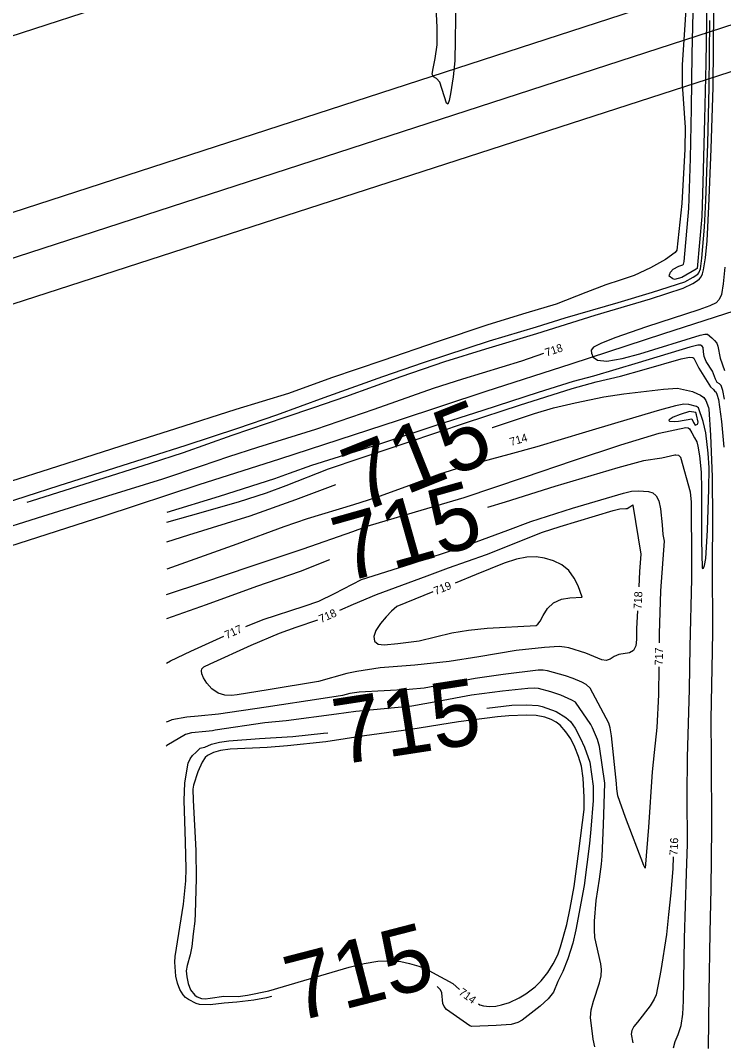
# Model space of a CAD drawing. Extents: x -468556195 to 3353078, y -306091294 to 1252632.
# Drawn here: x 1829375 to 1829727, y 533219 to 533730 of the extents above; entities that cross this region are included whole.
import ezdxf

# ---------------------------------------------------------------- set-up
doc = ezdxf.new("R2010")
doc.units = 0
for name, color, linetype in [('Default', 7, 'Continuous'), ('DT_X_Contour_Minor', 7, 'Continuous'), ('Level 14', 7, 'Continuous'), ('Level 19', 7, 'Continuous'), ('SC_Shading3', 7, 'Continuous')]:
    doc.layers.add(name, color=color, linetype=linetype)

msp = doc.modelspace()

# ---------------------------------------------------------------- linework, layer by layer
at = {"layer": 'Default'}
msp.add_lwpolyline([(1827162.83, 532893.73), (1827168.81, 532875.29), (1833162.58, 534815.33), (1833154.87, 534839.74)], close=True, dxfattribs=at)
at = {"layer": 'DT_X_Contour_Minor'}
for points in [[(1829593.13, 533741.62), (1829592.52, 533709.77), (1829591.78, 533701.79), (1829590.46, 533693.14), (1829589.79, 533689.85), (1829589.1, 533688.08), (1829588.36, 533688.52), (1829585.06, 533699.08), (1829583.38, 533700.83), (1829581.9, 533701.67), (1829581.22, 533702.98), (1829581.7, 533705.94), (1829582.79, 533710.83), (1829583.69, 533717.68), (1829583.81, 533726.32), (1829582.3, 533757.27)], [(1829378.72, 533489.09), (1829380.91, 533489.79), (1829410.96, 533499.28), (1829440.36, 533508.53), (1829456.98, 533513.89), (1829481.21, 533522.55), (1829507.71, 533531.63), (1829522.13, 533536.44), (1829538.11, 533541.92), (1829565.71, 533551.87), (1829587.59, 533559.36), (1829608.12, 533565.77), (1829633.62, 533573.4), (1829662.76, 533582.52), (1829690.41, 533590.8), (1829706.72, 533596.08), (1829711.56, 533598.35), (1829713.88, 533599.83), (1829714.84, 533600.65), (1829715.67, 533601.69), (1829716.36, 533603.18), (1829716.93, 533605.28), (1829717.83, 533611.29), (1829718.62, 533619.69), (1829719.59, 533636.83), (1829720.65, 533665.7), (1829721.64, 533696.62), (1829721.81, 533716.38), (1829722.15, 533752.87)], [(1829708.39, 533741.08), (1829707.56, 533727.79), (1829706.13, 533707.75), (1829706.23, 533697.89), (1829707.7, 533676.46), (1829707.48, 533665.58), (1829706.06, 533638.36), (1829703.51, 533615.12), (1829702.76, 533613.83), (1829697.94, 533610.42), (1829690.35, 533606.16), (1829682.12, 533602.4), (1829675.13, 533600.01), (1829668.05, 533597.7), (1829658.12, 533593.93), (1829643.22, 533588.14), (1829628.04, 533583.56), (1829609.05, 533577.7), (1829583.8, 533569.27), (1829556.59, 533559.93), (1829530.97, 533551.16), (1829509.35, 533543.36), (1829483.02, 533535.34), (1829452.87, 533525.69), (1829425.66, 533517.12), (1829393.98, 533506.94), (1829366.76, 533498.24)], [(1829718.54, 533740.23), (1829717.94, 533708.57), (1829717.39, 533680.55), (1829716.57, 533649.02), (1829715.97, 533631.83), (1829713.61, 533605.93), (1829713.16, 533605.56), (1829705.98, 533601.39), (1829702.3, 533600.4), (1829701.54, 533600.67), (1829699.68, 533602.02), (1829699.8, 533602.77), (1829700.39, 533604.08), (1829701.76, 533605.5), (1829704.56, 533607.06), (1829706.55, 533607.66), (1829706.92, 533608.07), (1829707.17, 533609.36), (1829709.53, 533635.89), (1829710.31, 533660.95), (1829710.85, 533685.8), (1829711.17, 533713.12), (1829711.9, 533741.05)], [(1829361.65, 533486.79), (1829394.74, 533497.34), (1829422.62, 533506.16), (1829458.2, 533517.49), (1829484.15, 533526.01), (1829503.57, 533532.66), (1829527.32, 533541.36), (1829556.6, 533551.94), (1829576.88, 533558.97), (1829609.82, 533569.67), (1829633.38, 533576.81), (1829647.71, 533581.21), (1829674.24, 533588.83), (1829691.31, 533593.98), (1829707.53, 533599.25), (1829711.76, 533601.6), (1829714, 533603.1), (1829714.59, 533603.75), (1829715.3, 533605.76), (1829715.96, 533610.98), (1829717.33, 533626.63), (1829718.02, 533639.88), (1829718.97, 533668.33), (1829719.64, 533696.58), (1829719.99, 533729.95)], [(1829727.57, 533606.61), (1829726.73, 533598.3), (1829725.78, 533592.93), (1829724.74, 533590.46), (1829723.19, 533588.77), (1829720.03, 533587.21), (1829714.44, 533585.16), (1829688.39, 533576.66), (1829672.61, 533571.15), (1829665.58, 533568.43), (1829661.79, 533566.51), (1829660.64, 533565.05), (1829660.9, 533563.53), (1829661.75, 533561.63), (1829663.94, 533560.02), (1829668.6, 533559.6), (1829676.27, 533560.94), (1829685.09, 533563.29), (1829715.18, 533572.57), (1829717.6, 533573.11), (1829718.88, 533573.01), (1829721.06, 533571.3), (1829722.38, 533569.96), (1829723.45, 533568.51), (1829724.01, 533567.06), (1829725.2, 533561.05), (1829727.34, 533554.88)], [(1829727.31, 533540.6), (1829726.47, 533544.97), (1829725.63, 533547.34), (1829724.82, 533548.25), (1829723.64, 533548.98), (1829722.91, 533550.53), (1829721.29, 533554.63), (1829718.24, 533559.38), (1829717.15, 533561.87), (1829716.85, 533564.24), (1829716.62, 533566.41), (1829716.17, 533567.12), (1829715.35, 533567.51), (1829714.09, 533567.54), (1829709.98, 533566.55), (1829684.2, 533558.75), (1829661.79, 533552.13), (1829651.65, 533549.46), (1829634.13, 533543.91), (1829606.5, 533534.95), (1829583.04, 533527.32), (1829554.42, 533517.96), (1829520.99, 533507.38), (1829509.71, 533503.45), (1829502.34, 533500.72), (1829474.75, 533491.94), (1829448.63, 533483.94)], [(1829340.43, 533467.61), (1829359.01, 533473.44), (1829386.56, 533482.07), (1829419.13, 533492.22), (1829446.62, 533500.73), (1829466, 533507.16), (1829479.52, 533511.96), (1829494.08, 533516.58), (1829523.05, 533525.58), (1829552.25, 533535.63), (1829581.87, 533546.04), (1829596.49, 533550.81), (1829626.01, 533559.81), (1829637.09, 533563.48)], [(1829448.61, 533479.07), (1829460.36, 533482.46), (1829484.44, 533489.21), (1829498.47, 533493.74), (1829508.3, 533497.4), (1829529.43, 533505.76), (1829545.26, 533511.12), (1829568.67, 533518.96), (1829598.46, 533528.87), (1829624.91, 533537.64), (1829651.29, 533545.97), (1829663.26, 533549.15), (1829675.43, 533552.12), (1829687.15, 533555.46), (1829705.64, 533560.81), (1829709.8, 533561.55), (1829711.53, 533561.43), (1829712.02, 533561.1), (1829712.92, 533559.45), (1829714.45, 533556.09), (1829720.35, 533546.67), (1829721.79, 533545.37), (1829722.47, 533544.48), (1829722.96, 533544.15), (1829723.59, 533543.11), (1829724.31, 533540.4), (1829725.83, 533529.44), (1829727.03, 533516.51)], [(1829611.2, 533526.38), (1829611.31, 533526.41), (1829632.43, 533533.43), (1829641.89, 533536.15), (1829652.64, 533538.69), (1829667.04, 533541.7), (1829677.1, 533543.3), (1829696.78, 533545.6), (1829703.79, 533546.08), (1829711.3, 533544.46), (1829711.69, 533544.2), (1829715.42, 533542.63), (1829716.95, 533541.48), (1829718.06, 533539.96), (1829719.4, 533536.35), (1829719.59, 533535.49), (1829720.41, 533522.55), (1829721.25, 533501.81), (1829721.29, 533480.24), (1829721.16, 533458.14), (1829721.29, 533424.34), (1829721.25, 533414.56), (1829720.57, 533380.66), (1829720.66, 533361.51), (1829720.78, 533326.29), (1829720.52, 533295.7), (1829719.99, 533274.01), (1829719.45, 533243.53), (1829719.19, 533215.99)], [(1829448.5, 533442.88), (1829467.15, 533449.1), (1829490.33, 533456.96), (1829516.73, 533465.75), (1829541.64, 533474.43), (1829548.76, 533477.07), (1829572.96, 533484.16), (1829597.22, 533491.39), (1829627.41, 533501.65), (1829651.82, 533509.88), (1829675.5, 533517.69), (1829694.65, 533523.55), (1829707.99, 533526.32), (1829709.16, 533526.27), (1829709.83, 533525.76), (1829711, 533523.67), (1829712.28, 533521.29), (1829713.45, 533519.18), (1829714.08, 533517.04), (1829714.83, 533512.21), (1829715.66, 533504.04), (1829715.89, 533495.74), (1829715.93, 533470.11), (1829716.11, 533456.21), (1829716.38, 533455.98), (1829716.83, 533456.15), (1829717.4, 533457.43), (1829717.98, 533460.92), (1829718.92, 533475), (1829719.6, 533495.6), (1829719.62, 533506.29), (1829719.11, 533513.51), (1829718.09, 533523.76), (1829716.62, 533529.34), (1829714.39, 533536.31), (1829713.43, 533536.9), (1829709.55, 533537.95), (1829707.07, 533538.02), (1829702.79, 533537.26), (1829694.83, 533535.01), (1829674.07, 533528.85), (1829657.9, 533523.99), (1829633.53, 533516.74), (1829619.47, 533512.82), (1829596.01, 533506.56), (1829584.87, 533503), (1829568.04, 533496.77), (1829552.88, 533491.16), (1829541.97, 533487.76), (1829518.7, 533480.79), (1829507.04, 533476.76), (1829483.62, 533468.12), (1829455.57, 533458.11), (1829448.54, 533455.65)], [(1829712.99, 533533.85), (1829709.88, 533534.48), (1829705.11, 533532.98), (1829701.61, 533531.57), (1829699.65, 533530.22), (1829699.45, 533529.82), (1829699.82, 533529.57), (1829702.2, 533529.35), (1829704.29, 533529.56), (1829710.94, 533530.76), (1829711.82, 533528.97), (1829712.63, 533527.63), (1829713.85, 533528.01), (1829714.09, 533528.35), (1829714.14, 533529.05), (1829713.3, 533532.72), (1829712.99, 533533.85)], [(1829701.85, 533216.19), (1829702.64, 533219.42), (1829704.16, 533223.01), (1829705.64, 533227.47), (1829706.48, 533233.16), (1829706.79, 533239.84), (1829707.3, 533270.88), (1829708.39, 533303.65), (1829708.82, 533318.14), (1829708.76, 533342.41), (1829708.82, 533361.44), (1829709.88, 533395.53), (1829710.25, 533416.81), (1829710.97, 533450.67), (1829711.08, 533458.75), (1829710.79, 533489.2), (1829710.37, 533494.03), (1829705.58, 533511.44), (1829704.58, 533512.46), (1829703.09, 533512.61), (1829702.48, 533512.57), (1829696, 533511.07), (1829686.84, 533509.66), (1829674.1, 533506.17), (1829642.49, 533496.85), (1829617.67, 533489.1), (1829608.86, 533486.38)], [(1829448.58, 533469.23), (1829459.58, 533472.82), (1829490.18, 533482.23), (1829513.14, 533490.37), (1829533.06, 533497.93)], [(1829488.03, 533426.99), (1829496.69, 533430.4), (1829517.29, 533437.08), (1829524.61, 533439.62), (1829532.4, 533443.45), (1829545.99, 533450.34), (1829570.77, 533458.3), (1829596.85, 533466.91), (1829619.11, 533475.06), (1829630.61, 533479.34), (1829651.37, 533485.99), (1829676.89, 533493.62), (1829680.85, 533494.6), (1829684.35, 533494.8), (1829689.32, 533494.47), (1829691.5, 533493.77), (1829693.27, 533492.3), (1829694.57, 533489.66), (1829695.41, 533485.72), (1829696.11, 533477.77), (1829696.59, 533472.89), (1829697.12, 533469.54), (1829695.28, 533444.81), (1829694.69, 533423.19), (1829694.64, 533418.76)], [(1829535.16, 533435.03), (1829541.87, 533438.08), (1829553.4, 533442.85), (1829578.65, 533452.25), (1829589.45, 533456.23), (1829608.47, 533462.96), (1829636.31, 533474.07), (1829645.23, 533476.94), (1829671.76, 533484.94), (1829675.11, 533485.77), (1829678.1, 533485.87), (1829678.73, 533485.84), (1829680.1, 533486.73), (1829681.55, 533487.77), (1829681.6, 533487.55), (1829685.49, 533463.07), (1829684.9, 533454.42), (1829684.48, 533446.78)], [(1829529.92, 533460.26), (1829515.23, 533454.44), (1829493.45, 533446.89), (1829468.2, 533437.68), (1829448.46, 533430.75)], [(1829581.54, 533444.17), (1829563.59, 533436.83), (1829560.9, 533434.51), (1829558.26, 533431.79), (1829555.35, 533428.39), (1829553.03, 533424.91), (1829552, 533421.87), (1829552.38, 533419.54), (1829554.16, 533418.13), (1829557.19, 533417.71), (1829564.12, 533418.4), (1829574.7, 533419.69), (1829591.13, 533423.71), (1829599.45, 533425.15), (1829608.7, 533426.05), (1829633.14, 533427.37), (1829634.07, 533428.01), (1829635.25, 533429.64), (1829636.74, 533432.49), (1829638.83, 533435.85), (1829641.83, 533438.76), (1829645.84, 533440.5), (1829650.08, 533441.27), (1829656.23, 533441.65), (1829654.17, 533447.25), (1829652.28, 533451.14), (1829649.56, 533454.89), (1829645.97, 533457.78), (1829641.8, 533459.79), (1829637.46, 533461.05), (1829633.17, 533461.68), (1829628.63, 533461.55), (1829623.4, 533460.51), (1829617.28, 533458.53), (1829603.28, 533452.88), (1829592.67, 533448.65)], [(1829683.83, 533434.8), (1829683.35, 533425.93), (1829683.36, 533420.47), (1829683.01, 533417.29), (1829681.94, 533414.83), (1829679.9, 533413.67), (1829674.57, 533412.87), (1829672.21, 533411.85), (1829670.13, 533410.65), (1829668.15, 533409.94), (1829666.1, 533410.18), (1829658.05, 533413.59), (1829649.5, 533416.18), (1829647.3, 533416.64), (1829644.74, 533416.84), (1829637.45, 533416.49), (1829623.19, 533414.84), (1829604.5, 533411.81), (1829589.73, 533409.37), (1829572.53, 533407.53), (1829555.28, 533406.2), (1829543.62, 533404.46), (1829538.5, 533403.36), (1829524.38, 533399.39), (1829499.2, 533395.2), (1829483.71, 533392.71), (1829480.9, 533392.47), (1829477.58, 533392.62), (1829474.19, 533393.63), (1829471.14, 533395.76), (1829468.64, 533398.52), (1829466.91, 533401.22), (1829466.06, 533403.29), (1829465.9, 533404.75), (1829466.15, 533405.74), (1829467.11, 533406.81), (1829470.33, 533408.32), (1829490.71, 533417.55), (1829504.93, 533423.58), (1829513.33, 533426.5), (1829524.13, 533430.28)], [(1829448.39, 533408.66), (1829450.41, 533409.7), (1829460.61, 533414.62), (1829477.07, 533422.1)], [(1829694.49, 533406.76), (1829694.32, 533392.73), (1829693.61, 533376.41), (1829692.24, 533363.93), (1829691.18, 533354.19), (1829689.38, 533326.57), (1829687.71, 533306.17), (1829687, 533307.36), (1829677.9, 533331.35), (1829674.09, 533342.26), (1829673.57, 533345.73), (1829673.44, 533348.5), (1829670.81, 533372.23), (1829670.14, 533376.32), (1829669.5, 533378.54), (1829660.24, 533396.06), (1829658.15, 533397.98), (1829656.09, 533399.06), (1829651.64, 533400.91), (1829647.8, 533402.17), (1829638.87, 533404.74), (1829636.7, 533405.11), (1829634.28, 533405.06), (1829616.68, 533402.88), (1829602.73, 533400.92), (1829577.17, 533396.04), (1829569.74, 533395.43), (1829544.81, 533394.14), (1829540.04, 533393.4), (1829536.38, 533392.49), (1829526.72, 533390.9), (1829498.19, 533386.61), (1829474.48, 533383.1), (1829464.22, 533382.14), (1829458.63, 533381.61), (1829451.16, 533380.21), (1829449.19, 533379.48), (1829448.3, 533379.01)], [(1829662.49, 533216.83), (1829661.73, 533220.54), (1829660.39, 533231.37), (1829660.67, 533235.22), (1829661.83, 533239.68), (1829664.91, 533248.68), (1829665.73, 533252.29), (1829665.92, 533255.38), (1829665.58, 533258.33), (1829662.62, 533271.46), (1829662.35, 533275.19), (1829662.39, 533279.54), (1829663.27, 533289.95), (1829664.8, 533300.66), (1829665.86, 533308.08), (1829666.27, 533312.09), (1829666.88, 533327.77), (1829667.56, 533348.54), (1829664.88, 533366.94), (1829663.91, 533370.4), (1829661.34, 533376.27), (1829660.47, 533377.87), (1829652.92, 533389.16), (1829651.1, 533390.15), (1829645.54, 533392.6), (1829640.56, 533394.22), (1829634.4, 533395.87), (1829632.18, 533396.08), (1829629.13, 533395.96), (1829616.46, 533394.59), (1829600.88, 533392.54), (1829584.09, 533389.36), (1829571.12, 533387.1), (1829560.72, 533386.06), (1829543.09, 533384.4), (1829533.34, 533383.06), (1829508.33, 533379.82), (1829497.6, 533378.81), (1829472.69, 533375.07), (1829471.44, 533374.72), (1829468.09, 533374.39), (1829460.91, 533373.72), (1829457.94, 533372.93), (1829448.6, 533367.41), (1829448.26, 533367.15)], [(1829608.48, 533386.13), (1829621.03, 533387.59), (1829628.43, 533387.7), (1829634.28, 533387.34), (1829636.26, 533386.96), (1829643.27, 533384.4), (1829648.02, 533381.46), (1829650.34, 533379.43), (1829652.69, 533376.04), (1829655.28, 533371.29), (1829657.33, 533366.61), (1829659.99, 533359.08), (1829661.77, 533347.15), (1829661.77, 533339.9), (1829660.6, 533325.53), (1829659.89, 533318.39), (1829657.15, 533297.49), (1829653.12, 533275.24), (1829651.5, 533268.6), (1829649.05, 533260.8), (1829646.61, 533254.42), (1829644.05, 533249.42), (1829641.84, 533244.16), (1829639.15, 533240.71), (1829635.14, 533237.02), (1829626.24, 533230.08), (1829624.1, 533228.98), (1829620.66, 533228), (1829613.3, 533227.45), (1829601.07, 533226.88), (1829600.08, 533227.24), (1829588.36, 533235.5), (1829587.18, 533236.97), (1829586.58, 533238.5), (1829586.14, 533243.69), (1829585.41, 533245.2), (1829583.78, 533246.91)], [(1829604.43, 533238.32), (1829605.12, 533237.82), (1829606.81, 533237.27), (1829609.94, 533237.01), (1829613.12, 533237.16), (1829615.9, 533237.76), (1829619.94, 533239.01), (1829624.71, 533241.23), (1829628.06, 533243.25), (1829632.76, 533246.82), (1829635.64, 533249.74), (1829638.97, 533253.88), (1829641.73, 533258.29), (1829643.97, 533262.76), (1829645.45, 533266.76), (1829648.46, 533277.97), (1829650.29, 533286.12), (1829652.21, 533296.88), (1829654.58, 533314.61), (1829657.17, 533335.4), (1829657.27, 533341.53), (1829656.71, 533351.01), (1829655.79, 533357.16), (1829654.41, 533361.97), (1829652.62, 533366.64), (1829650.48, 533370.74), (1829647.97, 533374.26), (1829645.22, 533377.5), (1829643.16, 533379.11), (1829640.66, 533380.47), (1829637.52, 533381.54), (1829633.18, 533382.36), (1829628.41, 533382.51), (1829619.61, 533382.29), (1829613.89, 533381.76), (1829594.47, 533379.27), (1829570.52, 533375.48), (1829547.36, 533372.24), (1829528.06, 533369.32), (1829508.89, 533367.23), (1829498.83, 533366.47), (1829480.19, 533365.64), (1829475.45, 533364.89), (1829471.86, 533363.88), (1829468.96, 533362.44), (1829467.81, 533361.36), (1829466.26, 533359.11), (1829464.02, 533354.22), (1829461.94, 533347.61), (1829461.65, 533345.55), (1829461.77, 533340.07), (1829463.09, 533314.84), (1829463.34, 533300.87), (1829462.81, 533283.44), (1829462.54, 533279.56), (1829461.84, 533273.34), (1829461.16, 533266.93), (1829460.31, 533262.83), (1829458.74, 533257.38), (1829458.24, 533254.79), (1829458.53, 533251.78), (1829459.31, 533248.51), (1829460.51, 533245.21), (1829462.59, 533242.62), (1829463.84, 533241.7), (1829465.87, 533240.87), (1829467.73, 533240.7), (1829470.2, 533241.02), (1829477.17, 533242.07), (1829484.2, 533241.89), (1829488.86, 533242.63), (1829499.54, 533244.77), (1829517.12, 533249.9), (1829539.67, 533256.67), (1829547.24, 533258.47), (1829554.05, 533259.6), (1829558.74, 533259.79), (1829565.54, 533259.37), (1829569.97, 533258.51), (1829574.6, 533257.1), (1829578.46, 533255.61), (1829581.46, 533253.99), (1829591.49, 533248.48), (1829593.29, 533246.93), (1829594.82, 533245.51)], [(1829500.98, 533241.94), (1829498.43, 533241.26), (1829492.14, 533240.08), (1829483.61, 533239.17), (1829477.26, 533238.54), (1829470.33, 533237.78), (1829464.9, 533237.88), (1829463.22, 533238.44), (1829459.42, 533240.36), (1829457.96, 533241.4), (1829456.75, 533242.74), (1829455.13, 533245.47), (1829453.96, 533248.6), (1829453.16, 533252.05), (1829452.59, 533259.08), (1829452.84, 533261.92), (1829456.91, 533288.15), (1829458.05, 533299.77), (1829458.22, 533305.77), (1829457.92, 533319.33), (1829457.21, 533339.97), (1829457.64, 533348.82), (1829459.33, 533358.52), (1829460.3, 533360.79), (1829461.45, 533362.35), (1829463.34, 533364.14), (1829465.2, 533366.06), (1829465.97, 533366.31), (1829467.65, 533366.66), (1829470.95, 533368.04), (1829474.96, 533369.02), (1829479.65, 533369.68), (1829494.9, 533370.86), (1829511.58, 533371.91), (1829526.85, 533373.5), (1829529.04, 533373.81)], [(1829701.77, 533311.79), (1829701.47, 533305.91), (1829700.45, 533293.8), (1829699.31, 533282.99), (1829698.29, 533272.98), (1829695.54, 533254.96), (1829693.22, 533242.83), (1829692.26, 533240.55), (1829690.23, 533237.25), (1829683.86, 533229.14), (1829682.1, 533226.9), (1829680.99, 533224.98), (1829680.65, 533223.09), (1829681.6, 533218.75)]]:
    msp.add_lwpolyline(points, dxfattribs=at)
at = {"layer": 'Level 14'}
msp.add_lwpolyline([(1830098.37, 533704.05), (1830058.74, 533691.03), (1830012.54, 533676.09), (1829969.08, 533661.83), (1829925.6, 533647.63), (1829881.16, 533632.98), (1829840.48, 533619.77), (1829797, 533605.52), (1829757.84, 533592.86), (1829696.87, 533573.2), (1829650.56, 533558.13), (1829608.04, 533544.33), (1829564.26, 533529.95), (1829504.85, 533510.57), (1829464.63, 533497.68), (1829417.11, 533482.13), (1829369.91, 533466.93)], dxfattribs=at)
at = {"layer": 'SC_Shading3'}
for points in [[(1827130.09, 532994.55), (1827117.12, 533034.5), (1834723.97, 535511.59), (1834739.18, 535464.89)], [(1827156.03, 532914.66), (1827168.81, 532875.29), (1833162.58, 534815.33), (1833148.11, 534860.04)]]:
    msp.add_lwpolyline(points, close=True, dxfattribs=at)

# ---------------------------------------------------------------- texts
at = {"layer": 'Level 19'}
for s, height, rotation, p in [('718', 4, 18.3518, (1829638.44, 533561.82)), ('715', 33, 21.7208, (1829545.2, 533483.5)), ('714', 4, 16.2548, (1829620.64, 533517.15)), ('715', 33, 15.7506, (1829537.44, 533448.69)), ('719', 4, 21.7323, (1829582.95, 533442.62)), ('718', 4, 86.8948, (1829685.87, 533435.44)), ('718', 4, 24.0299, (1829525.71, 533428.61)), ('717', 4, 24.4538, (1829478.57, 533420.59)), ('717', 4, 89.3184, (1829696.5, 533407.47)), ('715', 33, 8.7663, (1829534.4, 533357.67)), ('716', 4, 87.1182, (1829703.8, 533312.33)), ('715', 33, 14.4844, (1829512.89, 533229.08)), ('714', 4, 324.2483, (1829594.16, 533243.24))]:
    msp.add_text(s, height=height, rotation=rotation, dxfattribs=at).set_placement(p)

doc.saveas('drawing.dxf')
